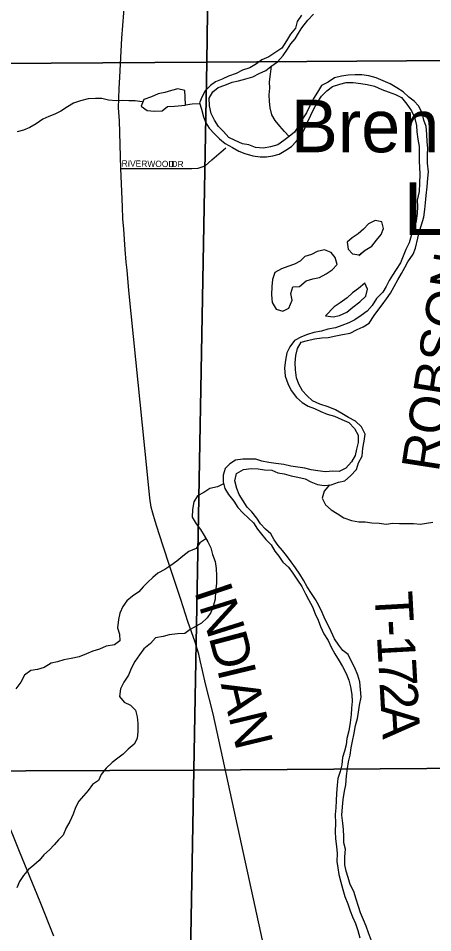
# Model space of a CAD drawing. Extents: x 1857828 to 2277390, y 930619 to 1324581.
# Drawn here: x 2080113 to 2083406, y 1203140 to 1210395 of the extents above; entities that cross this region are included whole.
import ezdxf

# ---------------------------------------------------------------- set-up
doc = ezdxf.new("R2010")
doc.units = 0
for name, color, linetype in [('GM_X_County_Road', 7, 'Continuous'), ('GM_X_County_Road_Text', 7, 'Continuous'), ('GM_X_Major_River', 7, 'Continuous'), ('GM_X_Minor_Lake', 7, 'Continuous'), ('GM_X_Minor_River', 7, 'Continuous'), ('GM_X_Rail_Line', 7, 'Continuous'), ('GM_X_Section', 7, 'Continuous'), ('GM_X_Township_Road_Text', 7, 'Continuous'), ('GM_X_Township_Subdivision', 7, 'Continuous'), ('GM_X_Township_Subdivision_Text', 7, 'Continuous'), ('GM_X_Unincorporated_Text', 7, 'Continuous')]:
    doc.layers.add(name, color=color, linetype=linetype)

msp = doc.modelspace()

# ---------------------------------------------------------------- linework, layer by layer
at = {"layer": 'GM_X_County_Road'}
msp.add_lwpolyline([(2082175, 1202521.8), (2081661.5, 1204876.2), (2081602.1, 1205114.6), (2081577.5, 1205220.8), (2081559.1, 1205298.9), (2081546.8, 1205351), (2081518.2, 1205445.1), (2081461.2, 1205609.2), (2081404.2, 1205783.4), (2081357.4, 1205927.6), (2081308.5, 1206069.8), (2081233.1, 1206306.1), (2081200.6, 1206404.2), (2081182.2, 1206468.3), (2081169.9, 1206516.4), (2081159.5, 1206588.5), (2081136.3, 1206801), (2081009.3, 1208054.2), (2080992.3, 1208234.7), (2080977.4, 1208397.1), (2080971.1, 1208459.3), (2080962.5, 1208561.6), (2080951.6, 1208722), (2080945.1, 1208804.2), (2080942.6, 1208900.5), (2080929.1, 1209204.5), (2080916.9, 1209582.5), (2080910.3, 1209684.8), (2080911.9, 1209759), (2080915.5, 1209837.3), (2080921, 1209927.6), (2080937.3, 1210236.7), (2080999.8, 1211044.3)], dxfattribs=at)
at = {"layer": 'GM_X_Major_River'}
for points in [[(2082364.8, 1210418.7), (2082328.9, 1210370.3), (2082315.1, 1210318.1), (2082275.2, 1210269.7), (2082243.4, 1210217.3), (2082207.6, 1210158.9), (2082151.6, 1210120.5), (2082103.6, 1210090.2), (2082049.6, 1210065.8), (2082005.6, 1210033.4), (2081953.6, 1210003.1), (2081895.5, 1209984.7), (2081843.5, 1209958.4), (2081783.5, 1209936), (2081733.5, 1209911.7), (2081681.4, 1209891.3), (2081639.5, 1209861), (2081599.6, 1209818.6), (2081573.7, 1209774.3), (2081553.8, 1209724.1)], [(2081659.7, 1209812.9), (2081701.7, 1209845.2), (2081755.7, 1209865.6), (2081813.8, 1209888), (2081863.8, 1209900.2), (2081921.9, 1209914.6), (2081976, 1209930.9), (2082028, 1209957.3), (2082080, 1209981.6), (2082120, 1210011.9), (2082171.9, 1210050.3), (2082217.8, 1210100.8), (2082251.7, 1210149.1), (2082279.6, 1210193.4), (2082313.5, 1210231.7), (2082339.4, 1210276), (2082367.2, 1210320.3), (2082415.1, 1210380.8), (2082459, 1210427.2)], [(2082266.8, 1209458.5), (2082229.4, 1209497.3), (2082191.1, 1209539.2), (2082154.8, 1209583.2), (2082128.4, 1209629.2), (2082114.1, 1209685.4), (2082109.8, 1209735.6), (2082107.5, 1209787.8), (2082111.2, 1209840.1), (2082109, 1209890.3), (2082116.7, 1209950.6), (2082126, 1210016.4)], [(2082846.9, 1206921.3), (2082850.6, 1206985.6), (2082862.4, 1207039.9), (2082870.2, 1207096.1), (2082839.8, 1207154.2), (2082791.5, 1207198.1), (2082737.3, 1207228), (2082685, 1207259.9), (2082632.8, 1207289.7), (2082574.5, 1207313.6), (2082510.3, 1207333.3), (2082450, 1207361.1), (2082405.8, 1207401.1), (2082371.5, 1207439.1), (2082343.2, 1207493.1), (2082323, 1207543.2), (2082316.7, 1207605.5), (2082312.4, 1207661.7), (2082318.2, 1207719.9), (2082332, 1207774.2), (2082361.9, 1207824.5), (2082411.9, 1207838.8), (2082468, 1207851.1), (2082524.1, 1207859.4), (2082576.2, 1207863.7), (2082636.3, 1207876.1), (2082690.4, 1207886.3), (2082750.5, 1207896.7), (2082806.5, 1207925.1), (2082852.5, 1207947.4), (2082900.5, 1207975.7), (2082940.3, 1208036.1), (2082970.2, 1208076.4), (2083004.1, 1208122.8), (2083038, 1208169.1), (2083069.9, 1208215.5), (2083099.7, 1208267.8), (2083129.6, 1208320.2), (2083159.4, 1208370.5), (2083185.3, 1208418.8), (2083209.1, 1208463.1), (2083251, 1208523.6), (2083268.8, 1208571.8), (2083288.5, 1208650.2), (2083302.3, 1208706.5), (2083318.2, 1208756.8), (2083335.9, 1208817.1), (2083343.7, 1208877.4), (2083349.5, 1208931.6), (2083355.2, 1208989.9), (2083363, 1209058.2), (2083368.7, 1209126.5), (2083372.5, 1209176.7), (2083364.2, 1209246.9), (2083365.9, 1209315.2), (2083367.7, 1209365.4), (2083361.4, 1209415.6), (2083359.2, 1209475.8), (2083352.9, 1209536), (2083336.7, 1209588.1), (2083322.4, 1209646.3), (2083294.1, 1209700.4), (2083259.8, 1209738.4), (2083215.6, 1209768.3), (2083171.3, 1209812.2), (2083121.1, 1209842.1), (2083068.8, 1209876), (2083012.6, 1209897.8), (2082956.3, 1209921.6), (2082898.1, 1209939.4), (2082842, 1209947.2), (2082789.8, 1209946.9), (2082735.7, 1209942.6), (2082681.6, 1209936.3), (2082625.5, 1209922), (2082575.6, 1209887.6), (2082521.6, 1209861.3), (2082491.7, 1209808.9), (2082457.8, 1209758.6), (2082430, 1209700.2), (2082404.2, 1209643.9), (2082372.3, 1209597.5), (2082342.5, 1209545.2), (2082308.6, 1209492.8), (2082266.7, 1209458.5), (2082224.7, 1209426.1), (2082176.7, 1209391.8), (2082116.7, 1209375.4), (2082062.6, 1209365.1), (2081998.4, 1209370.8), (2081944.2, 1209390.6), (2081894, 1209400.4), (2081837.8, 1209426.3), (2081787.6, 1209448.1), (2081743.3, 1209498.1), (2081705, 1209536.1), (2081672.7, 1209586.1), (2081646.4, 1209640.2), (2081632.1, 1209700.3), (2081629.9, 1209760.6), (2081659.7, 1209812.9)], [(2081553.8, 1209724.1), (2081570.1, 1209673.9), (2081586.4, 1209613.8), (2081602.6, 1209565.7), (2081630.9, 1209523.6), (2081673.2, 1209479.7), (2081711.4, 1209439.7), (2081757.7, 1209401.8), (2081816, 1209369.9), (2081866.2, 1209342.1), (2081912.4, 1209322.2), (2081976.6, 1209304.5), (2082034.8, 1209294.7), (2082084.9, 1209294.9), (2082137, 1209303.2), (2082187.1, 1209317.5), (2082239.1, 1209349.9), (2082283.1, 1209378.2), (2082321, 1209418.6), (2082362.9, 1209469), (2082390.7, 1209521.3), (2082412.5, 1209571.6), (2082438.4, 1209625.9), (2082460.2, 1209672.2), (2082488.1, 1209724.6), (2082523.9, 1209776.9), (2082563.8, 1209819.3), (2082609.8, 1209853.7), (2082667.9, 1209872), (2082719.9, 1209886.3), (2082774.1, 1209886.6), (2082834.2, 1209876.8), (2082884.4, 1209869.1), (2082944.6, 1209857.3), (2083000.8, 1209829.5), (2083053, 1209811.6), (2083109.3, 1209789.8), (2083157.5, 1209768), (2083201.8, 1209714), (2083238.1, 1209659.9), (2083262.4, 1209611.9), (2083278.7, 1209545.7), (2083280.9, 1209493.5), (2083287.2, 1209437.3), (2083299.5, 1209377.1), (2083299.7, 1209320.9), (2083297.9, 1209262.7), (2083302.2, 1209212.5), (2083304.4, 1209162.3), (2083300.7, 1209084), (2083299, 1209021.7), (2083283.2, 1208953.4), (2083285.4, 1208903.2), (2083283.7, 1208847), (2083273.9, 1208788.7), (2083260.2, 1208722.4), (2083236.3, 1208668), (2083218.5, 1208613.8), (2083192.7, 1208561.4), (2083170.9, 1208507.1), (2083151, 1208454.8), (2083115.2, 1208402.4), (2083087.3, 1208358.1), (2083059.4, 1208313.8), (2083035.6, 1208267.5), (2083009.7, 1208221.2), (2082959.8, 1208170.8), (2082925.9, 1208116.4), (2082886, 1208072), (2082838.1, 1208037.7), (2082788.1, 1208003.3), (2082740.1, 1207979), (2082684, 1207958.6), (2082634, 1207940.3), (2082573.9, 1207930), (2082521.9, 1207913.6), (2082461.8, 1207903.3), (2082411.7, 1207887), (2082363.7, 1207866.7), (2082307.7, 1207838.3), (2082269.8, 1207787.9), (2082247.9, 1207741.7), (2082236.2, 1207683.4), (2082228.4, 1207621.1), (2082234.7, 1207554.9), (2082255, 1207496.7), (2082281.3, 1207442.6), (2082323.6, 1207386.6), (2082369.9, 1207346.7), (2082416.1, 1207318.8), (2082466.3, 1207299), (2082516.6, 1207275.1), (2082566.8, 1207255.3), (2082625, 1207237.5), (2082683.2, 1207211.7), (2082739.5, 1207187.9), (2082783.8, 1207139.9), (2082814.1, 1207087.8), (2082814.3, 1207029.6), (2082800.5, 1206977.3), (2082790.7, 1206927.1)], [(2082268.2, 1209459.7), (2082268.2, 1209459.6)], [(2082790.7, 1206927.1), (2082760.2, 1206875.2), (2082716.4, 1206826.8), (2082662.4, 1206798.4), (2082612.3, 1206802.1), (2082554.1, 1206795.8), (2082494, 1206803.5), (2082441.8, 1206813.3), (2082389.6, 1206825.1), (2082333.4, 1206834.8), (2082279.3, 1206840.6), (2082223.1, 1206854.3), (2082160.9, 1206864), (2082104.7, 1206869.7), (2082048.5, 1206881.5), (2082000.3, 1206897.3), (2081950.2, 1206897), (2081898.1, 1206896.8), (2081840, 1206890.4), (2081794, 1206860.1), (2081758.1, 1206823.7), (2081740.3, 1206769.4), (2081740.6, 1206717.2), (2081754.9, 1206665), (2081783.2, 1206617), (2081825.5, 1206565), (2081857.8, 1206512.9), (2081898.1, 1206471), (2081942.5, 1206429.1), (2081982.7, 1206393.1), (2082013, 1206343.1), (2082045.3, 1206303.1), (2082079.6, 1206259.1), (2082121.9, 1206217.1), (2082152.2, 1206167.1), (2082182.5, 1206127.1), (2082214.8, 1206081.1), (2082261.1, 1206039.1), (2082295.4, 1205993.1), (2082331.8, 1205937.1), (2082366.1, 1205887), (2082396.5, 1205829), (2082418.7, 1205782.9), (2082451.1, 1205726.8), (2082473.4, 1205670.7), (2082495.7, 1205620.6), (2082516, 1205568.5), (2082540.3, 1205510.4), (2082576.7, 1205458.4), (2082599, 1205406.3), (2082629.3, 1205352.2), (2082661.7, 1205298.2), (2082690, 1205252.1), (2082718.3, 1205198), (2082740.6, 1205143.9), (2082752.9, 1205089.8), (2082763.2, 1205029.6), (2082767.5, 1204973.4), (2082761.7, 1204921.1), (2082758, 1204870.9), (2082750.3, 1204808.6), (2082738.5, 1204742.2), (2082722.8, 1204681.9), (2082719, 1204631.7), (2082705.3, 1204581.4), (2082689.5, 1204529.1), (2082683.7, 1204470.8), (2082670, 1204418.5), (2082652.2, 1204364.2), (2082648.4, 1204312), (2082642.7, 1204243.7), (2082639, 1204189.4), (2082635.3, 1204131.1), (2082631.5, 1204076.9), (2082633.9, 1204010.6), (2082632.2, 1203944.3), (2082634.5, 1203884.1), (2082640.8, 1203823.9), (2082647.1, 1203769.7), (2082645.4, 1203705.4), (2082651.6, 1203655.2), (2082659.9, 1203603.1), (2082676.2, 1203540.9), (2082692.6, 1203482.7), (2082708.9, 1203426.6), (2082731.2, 1203368.5), (2082751.5, 1203314.3), (2082767.8, 1203266.2), (2082792.1, 1203212.1), (2082812.4, 1203158), (2082826.7, 1203099.8)], [(2082919.1, 1203076.2), (2082896.7, 1203140.4), (2082878.4, 1203192.5), (2082856.1, 1203242.6), (2082833.8, 1203298.7), (2082815.5, 1203346.8), (2082797.2, 1203405), (2082778.8, 1203467.1), (2082750.5, 1203523.2), (2082734.2, 1203579.4), (2082717.9, 1203627.5), (2082707.6, 1203677.6), (2082707.3, 1203741.9), (2082713.1, 1203802.2), (2082698.8, 1203852.3), (2082700.5, 1203902.5), (2082698.3, 1203958.8), (2082692, 1204008.9), (2082683.7, 1204073.2), (2082689.4, 1204139.5), (2082695.1, 1204197.7), (2082704.8, 1204262.1), (2082716.6, 1204312.3), (2082722.2, 1204384.7), (2082730, 1204442.9), (2082737.7, 1204497.2), (2082751.5, 1204547.5), (2082757.3, 1204605.8), (2082769, 1204660.1), (2082782.7, 1204722.4), (2082792.5, 1204784.7), (2082808.2, 1204839), (2082816, 1204889.3), (2082823.8, 1204945.6), (2082837.5, 1205009.9), (2082833.2, 1205070.1), (2082826.9, 1205130.3), (2082810.6, 1205184.5), (2082786.2, 1205242.6), (2082761.9, 1205290.7), (2082733.6, 1205346.7), (2082693.3, 1205378.7), (2082661.1, 1205422.7), (2082624.7, 1205472.7), (2082598.4, 1205528.8), (2082578.1, 1205574.9), (2082551.8, 1205624.9), (2082527.5, 1205681.1), (2082501.2, 1205737.1), (2082474.9, 1205783.2), (2082442.6, 1205831.2), (2082408.2, 1205883.2), (2082379.9, 1205937.3), (2082349.6, 1205985.4), (2082317.3, 1206035.4), (2082280.9, 1206083.4), (2082244.6, 1206133.4), (2082212.3, 1206173.4), (2082178.1, 1206211.4), (2082145.8, 1206257.4), (2082119.5, 1206305.5), (2082077.2, 1206341.4), (2082036.9, 1206383.4), (2082008.6, 1206429.4), (2081970.3, 1206479.4), (2081932, 1206517.4), (2081899.7, 1206565.4), (2081869.4, 1206617.4), (2081849.1, 1206665.5), (2081834.7, 1206725.7), (2081848.5, 1206784), (2081902.5, 1206816.4), (2081962.6, 1206822.8), (2082018.7, 1206821.1), (2082068.9, 1206813.3), (2082127, 1206809.6), (2082175.3, 1206789.8), (2082225.4, 1206780), (2082281.6, 1206766.2), (2082333.8, 1206754.5), (2082394, 1206740.7), (2082438.2, 1206716.9), (2082490.5, 1206695.1), (2082544.6, 1206689.3), (2082600.7, 1206693.6), (2082658.8, 1206716), (2082708.9, 1206724.3), (2082752.8, 1206764.7), (2082800.6, 1206815.2), (2082816.4, 1206867.5), (2082846.9, 1206921.3)]]:
    msp.add_lwpolyline(points, dxfattribs=at)
at = {"layer": 'GM_X_Minor_Lake'}
for points in [[(2081443, 1209705.6), (2081439.8, 1209771.7), (2081437.5, 1209821.9), (2081381.3, 1209835.6), (2081331.2, 1209821.3), (2081277.1, 1209806.9), (2081225, 1209794.5), (2081171, 1209772.1), (2081111, 1209751.6), (2081089.2, 1209699.2), (2081137.5, 1209663.4)], [(2081443, 1209705.6), (2081439.8, 1209771.7), (2081437.5, 1209821.9), (2081381.3, 1209835.6), (2081331.2, 1209821.3), (2081277.1, 1209806.9), (2081225, 1209794.5), (2081171, 1209772.1), (2081111, 1209751.6), (2081089.2, 1209699.2), (2081137.5, 1209663.4)], [(2081137.5, 1209663.4), (2081195.7, 1209657.7), (2081255.9, 1209662.1), (2081299.8, 1209694.5), (2081353.9, 1209698.8), (2081443, 1209705.6)], [(2081137.5, 1209663.4), (2081195.7, 1209657.7), (2081255.9, 1209662.1), (2081299.8, 1209694.5), (2081353.9, 1209698.8), (2081443.1, 1209705.6)], [(2082818.4, 1208514.4), (2082868.3, 1208554.9), (2082922.3, 1208587.4), (2082960.2, 1208635.8), (2082998, 1208680.2), (2083015.8, 1208728.6), (2083001.5, 1208780.7), (2082949.3, 1208790.4), (2082897.3, 1208764), (2082857.4, 1208721.6)], [(2082822, 1208517.3), (2082868.3, 1208554.9), (2082922.3, 1208587.4), (2082960.2, 1208635.8), (2082998, 1208680.2), (2083015.8, 1208728.6), (2083001.5, 1208780.7), (2082949.3, 1208790.4), (2082897.3, 1208764), (2082857.4, 1208721.6)], [(2082857.4, 1208721.6), (2082813.5, 1208685.1), (2082767.5, 1208652.7), (2082727.6, 1208618.3), (2082733.9, 1208564.1), (2082770.2, 1208526.2), (2082822, 1208517.3)], [(2082348.5, 1208268.4), (2082400.4, 1208310.9), (2082454.4, 1208327.3), (2082506.5, 1208339.7), (2082558.5, 1208368.2), (2082608.5, 1208398.6), (2082648.4, 1208441), (2082630, 1208497.2), (2082599.7, 1208537.2), (2082547.5, 1208556.9), (2082489.4, 1208544.5), (2082443.4, 1208522.1), (2082389.3, 1208505.8), (2082353.4, 1208469.4)], [(2082353.4, 1208469.4), (2082309.4, 1208445), (2082255.4, 1208426.6), (2082205.3, 1208406.2), (2082151.3, 1208377.7), (2082133.6, 1208323.4), (2082127.9, 1208267.1), (2082124.2, 1208200.8), (2082130.6, 1208140.5), (2082163, 1208086.5), (2082215.2, 1208070.7), (2082263.2, 1208095.1), (2082290.9, 1208157.6), (2082278.6, 1208211.8), (2082294.4, 1208264.1), (2082348.5, 1208268.4)], [(2082554.3, 1208034.6), (2082614.5, 1208027), (2082664.6, 1208037.3), (2082722.6, 1208063.8), (2082770.6, 1208102.2), (2082828.5, 1208146.8), (2082874.3, 1208191.3), (2082888.1, 1208245.6), (2082865.8, 1208293.7)], [(2082865.8, 1208293.7), (2082815.9, 1208251.2), (2082769.9, 1208216.8), (2082726, 1208178.3), (2082672.1, 1208137.8), (2082622.1, 1208105.4), (2082554.3, 1208034.6)]]:
    msp.add_lwpolyline(points, dxfattribs=at)
at = {"layer": 'GM_X_Minor_River'}
for points in [[(2081097, 1209733.4), (2081042.8, 1209739.1), (2080992.7, 1209740.8), (2080940.5, 1209742.5), (2080890.4, 1209740.2), (2080830.2, 1209745.9), (2080778, 1209757.6), (2080725.9, 1209759.3), (2080669.7, 1209754.9), (2080607.6, 1209740.5), (2080551.6, 1209722.1), (2080505.6, 1209691.7), (2080451.7, 1209657.2), (2080403.6, 1209634.8), (2080355.6, 1209616.4), (2080309.6, 1209594), (2080255.7, 1209557.5), (2080205.7, 1209529.1), (2080155.7, 1209506.7), (2080105.6, 1209494.3)], [(2081556.6, 1209715.5), (2081496.2, 1209713.8), (2081442.1, 1209705.4)], [(2081744.9, 1206701.3), (2081696.7, 1206676.8), (2081636.6, 1206664.4), (2081588.6, 1206634), (2081536.6, 1206607.6), (2081508.8, 1206559.3), (2081497, 1206499), (2081495.3, 1206436.7), (2081525.7, 1206384.7), (2081562, 1206338.6), (2081590.3, 1206290.6), (2081618.6, 1206242.6), (2081642.9, 1206194.5), (2081657.2, 1206140.3), (2081677.5, 1206086.2), (2081685.8, 1206030), (2081688.1, 1205971.8), (2081688.3, 1205911.6), (2081680.6, 1205849.2), (2081676.9, 1205787), (2081661.2, 1205728.6), (2081643.4, 1205680.4), (2081613.5, 1205638), (2081569.6, 1205595.6), (2081525.6, 1205571.3), (2081479.6, 1205546.9), (2081437.7, 1205514.6), (2081377.5, 1205512.2), (2081311.4, 1205503.9), (2081263.4, 1205489.6), (2081203.3, 1205479.2), (2081163.4, 1205434.8), (2081111.5, 1205392.3), (2081075.6, 1205346), (2081039.8, 1205291.5), (2081010, 1205235.1), (2080988.2, 1205184.8), (2080952.4, 1205128.4), (2080924.6, 1205074), (2080918.9, 1205013.7), (2080955.2, 1204969.8), (2081005.4, 1204945.9), (2081043.7, 1204906), (2081058, 1204851.8), (2081062.3, 1204799.6), (2081064.6, 1204737.4), (2081058.8, 1204681.1), (2081035, 1204634.8), (2080987.1, 1204596.4), (2080947.2, 1204556), (2080905.2, 1204525.6), (2080859.3, 1204491.2), (2080811.4, 1204446.8), (2080771.5, 1204396.4), (2080749.7, 1204348.1), (2080703.7, 1204315.7), (2080667.9, 1204269.3), (2080632, 1204226.9), (2080594.1, 1204182.6), (2080568.3, 1204134.2), (2080550.5, 1204081.9), (2080522.7, 1204021.5), (2080494.9, 1203971.2), (2080471.1, 1203914.8), (2080433.2, 1203876.4), (2080399.3, 1203838.1), (2080361.4, 1203797.7), (2080315.5, 1203759.3), (2080279.6, 1203712.9), (2080237.7, 1203676.6), (2080195.8, 1203642.2), (2080155.9, 1203593.8), (2080122.1, 1203547.4), (2080102.3, 1203497.1)], [(2082585.2, 1206692.4), (2082544.9, 1206643.1), (2082527.1, 1206586.8), (2082553.4, 1206534.7), (2082599.7, 1206494.8), (2082648, 1206464.9), (2082700.3, 1206433.1), (2082760.5, 1206411.3), (2082818.7, 1206399.6), (2082868.8, 1206399.8), (2082923, 1206392.1), (2082981.1, 1206388.4), (2083037.3, 1206382.7), (2083089.4, 1206389), (2083143.5, 1206387.2), (2083199.7, 1206387.5), (2083253.8, 1206385.8), (2083308, 1206382.1), (2083358, 1206388.4), (2083408.1, 1206396.7)], [(2081604.7, 1206266.1), (2081556.5, 1206234.2), (2081526.6, 1206189.8), (2081468.6, 1206163.4), (2081420.7, 1206127), (2081372.7, 1206088.6), (2081324.8, 1206054.2), (2081276.8, 1206021.8), (2081222.8, 1205993.4), (2081182.9, 1205957.1), (2081143, 1205920.7), (2081107.1, 1205884.3), (2081071.2, 1205846), (2081021.2, 1205809.6), (2080975.3, 1205773.2), (2080945.5, 1205728.9), (2080919.6, 1205676.5), (2080909.9, 1205624.2), (2080902.2, 1205559.9), (2080918.5, 1205509.8), (2080920.7, 1205455.6), (2080876.8, 1205425.2), (2080810.7, 1205414.8), (2080758.7, 1205390.5), (2080706.6, 1205374.1), (2080654.6, 1205351.8), (2080598.6, 1205329.4), (2080532.5, 1205314.9), (2080474.4, 1205304.6), (2080426.3, 1205290.3), (2080374.3, 1205277.9), (2080320.3, 1205243.5), (2080266.3, 1205229.2), (2080214.2, 1205220.9), (2080164.2, 1205182.4), (2080134.4, 1205128.1), (2080094.6, 1205075.6)]]:
    msp.add_lwpolyline(points, dxfattribs=at)
at = {"layer": 'GM_X_Rail_Line'}
msp.add_lwpolyline([(2080397.1, 1203112.2), (2080286.3, 1203384.5), (2080123.5, 1203785.7), (2079882.9, 1204376.3)], dxfattribs=at)
at = {"layer": 'GM_X_Section'}
for points in [[(2076344.3, 1215732.7), (2081688.8, 1215745.2), (2081611.5, 1210047.1), (2076246.6, 1210012.2)], [(2086844.8, 1215767), (2086806.5, 1212949.4), (2086771.6, 1210288), (2086769.4, 1210081), (2081611.5, 1210047.1), (2081688.8, 1215745.2)], [(2081611.5, 1210047.1), (2086769.4, 1210081), (2086746, 1207929.3), (2086694.7, 1204467.4), (2081507.6, 1204431.1)], [(2076246.6, 1210012.2), (2081611.5, 1210047.1), (2081507.6, 1204431.1), (2076168.5, 1204407.7)], [(2081507.6, 1204431.1), (2081407.4, 1198863.1), (2076109.5, 1198829.7), (2076168.5, 1204407.7)], [(2086694.3, 1204440.7), (2086657.8, 1201547.9), (2086629.8, 1198875.6), (2081407.4, 1198863.1), (2081507.6, 1204431.1), (2086694.7, 1204467.4)]]:
    msp.add_lwpolyline(points, close=True, dxfattribs=at)
at = {"layer": 'GM_X_Township_Subdivision'}
msp.add_lwpolyline([(2080929.1, 1209204.5), (2081492.1, 1209202.5), (2081542.4, 1209207.1), (2081597.2, 1209225.3), (2081652.1, 1209271), (2081761.8, 1209367)], dxfattribs=at)

# ---------------------------------------------------------------- texts
at = {"layer": 'GM_X_County_Road_Text'}
for s, rotation, p in [('I', 288.61516, (2081508.1, 1205850.1)), ('N', 287.44421, (2081546.9, 1205734.9)), ('D', 284.827, (2081625.1, 1205486.5)), ('I', 283.56102, (2081692.2, 1205233)), ('A', 283.52294, (2081721.1, 1205113.3)), ('N', 283.5194, (2081782.8, 1204856.6))]:
    msp.add_text(s, height=300, rotation=rotation, dxfattribs=at).set_placement(p)
at = {"layer": 'GM_X_Township_Road_Text'}
for s, rotation, p in [('ROBSON', 81.17705, (2083453.1, 1206789.1)), ('T', 273.16866, (2082943.8, 1205840.8)), ('-', 273.17036, (2082956.2, 1205616.7)), ('1', 273.1657, (2082963, 1205493.7)), ('7', 273.17625, (2082973.3, 1205309.1)), ('2', 273.20927, (2082983.5, 1205124.4)), ('A', 273.49129, (2082993.9, 1204938.3))]:
    msp.add_text(s, height=300, rotation=rotation, dxfattribs=at).set_placement(p)
at = {"layer": 'GM_X_Township_Subdivision_Text'}
for s, rotation, p in [('RIVERWOOD', 359.32633, (2080934.4, 1209218.6)), ('DR', 0.00001, (2081330.3, 1209214.2))]:
    msp.add_text(s, height=50, rotation=rotation, dxfattribs=at).set_placement(p)
at = {"layer": 'GM_X_Unincorporated_Text'}
for s, p in [('Brentwood', (2082280.7, 1209332.1)), ('Lake', (2083178.3, 1208676.5))]:
    msp.add_text(s, height=417, rotation=0.00001, dxfattribs=at).set_placement(p)

doc.saveas('drawing.dxf')
